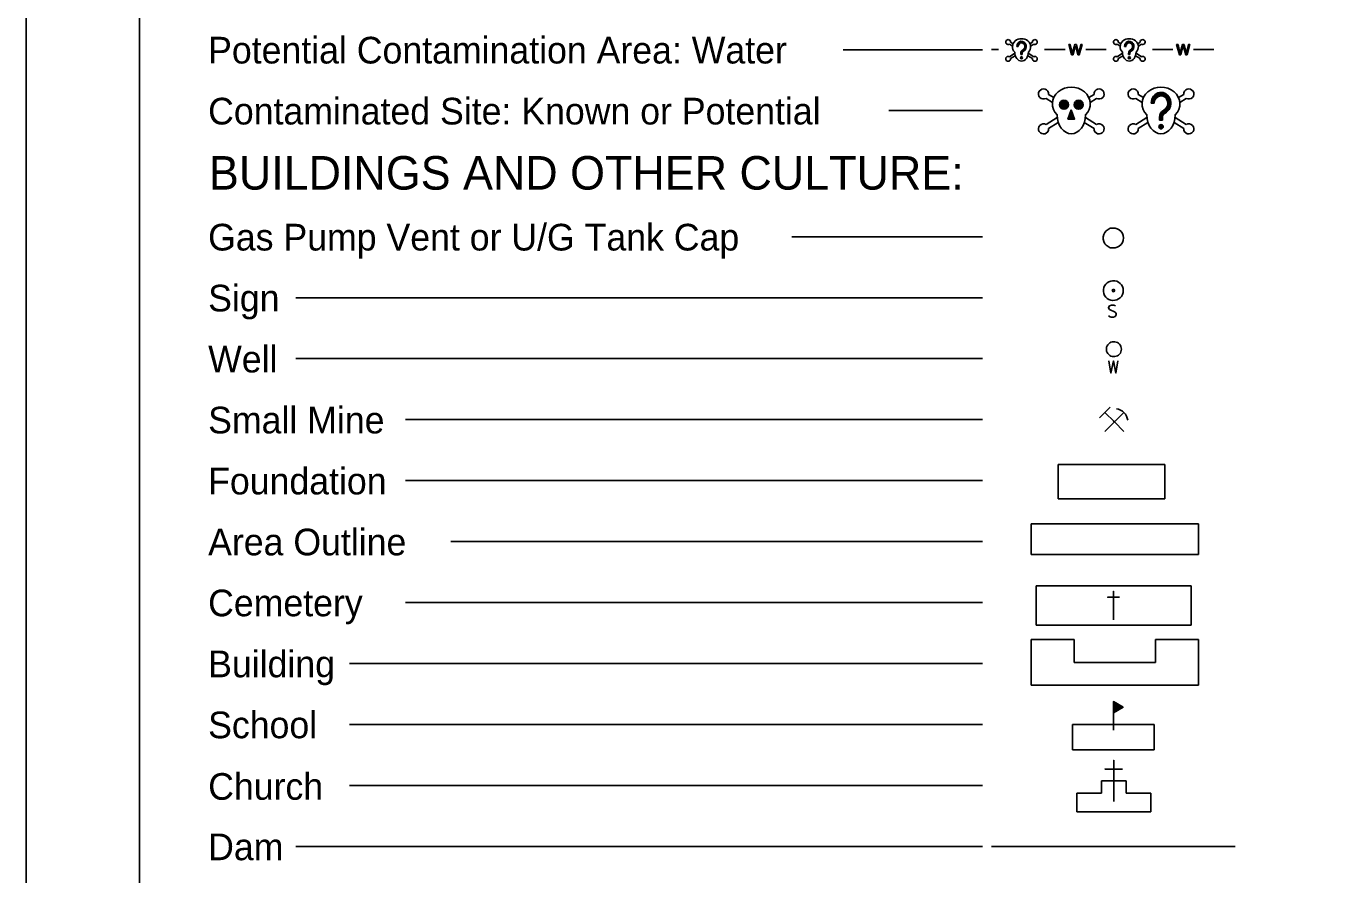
# Model space of a CAD drawing. Extents: x 1855058 to 1858918, y 1540202 to 1542502.
# Drawn here: x 1857118.6 to 1857551.6, y 1541678.1 to 1541959 of the extents above; entities that cross this region are included whole.
import ezdxf

# ---------------------------------------------------------------- set-up
doc = ezdxf.new("R2010")
doc.units = 0
for name, color, linetype in [('Default', 7, 'Continuous'), ('Exist Contamination Potential Cell', 7, 'Continuous'), ('Sheet Data Field CELL', 7, 'Continuous'), ('Sheet Symbology CELL', 7, 'Continuous')]:
    doc.layers.add(name, color=color, linetype=linetype)

msp = doc.modelspace()

# ---------------------------------------------------------------- linework, layer by layer
at = {"layer": 'Default'}
msp.add_lwpolyline([(1857118.6, 1542501.77), (1857118.6, 1541401.77), (1858818.6, 1541401.77), (1858818.6, 1542501.77)], close=True, dxfattribs=at)
at = {"layer": 'Exist Contamination Potential Cell'}
msp.add_line((1857118.6, 1542501.77), (1857118.6, 1541401.77), dxfattribs=at)
at = {"layer": 'Sheet Data Field CELL'}
for p, q in [((1857435.28, 1541951.18), (1857389.09, 1541951.18)), ((1857438.18, 1541951.19), (1857440.51, 1541951.19)), ((1857444.13, 1541953.02), (1857445.15, 1541952.38)), ((1857444.54, 1541953.67), (1857445.36, 1541953.15)), ((1857446.6, 1541952.24), (1857447.08, 1541952.24)), ((1857448.16, 1541951.19), (1857448.16, 1541951.19)), ((1857451.78, 1541953.67), (1857450.95, 1541953.15)), ((1857452.18, 1541953.02), (1857451.16, 1541952.38)), ((1857455.8, 1541951.19), (1857462.59, 1541951.19)), ((1857469.39, 1541951.19), (1857476.18, 1541951.19)), ((1857479.8, 1541953.02), (1857480.82, 1541952.38)), ((1857480.2, 1541953.67), (1857481.03, 1541953.15)), ((1857482.26, 1541952.24), (1857482.75, 1541952.24)), ((1857483.82, 1541951.19), (1857483.82, 1541951.19)), ((1857487.44, 1541953.67), (1857486.62, 1541953.15)), ((1857487.85, 1541953.02), (1857486.83, 1541952.38)), ((1857491.47, 1541951.19), (1857498.26, 1541951.19)), ((1857505.05, 1541951.19), (1857511.85, 1541951.19)), ((1857445.91, 1541949.98), (1857444.13, 1541948.86)), ((1857446.08, 1541949.19), (1857444.54, 1541948.22)), ((1857447.92, 1541949.97), (1857447.92, 1541949.55)), ((1857447.92, 1541949.55), (1857448.4, 1541949.55)), ((1857447.98, 1541949.97), (1857447.98, 1541949.55)), ((1857448.05, 1541949.97), (1857448.05, 1541949.55)), ((1857448.12, 1541949.97), (1857448.12, 1541949.55)), ((1857448.19, 1541949.97), (1857448.19, 1541949.55)), ((1857448.26, 1541949.97), (1857448.26, 1541949.55)), ((1857448.33, 1541949.97), (1857448.33, 1541949.55)), ((1857448.4, 1541949.97), (1857448.4, 1541949.55)), ((1857450.23, 1541949.19), (1857451.78, 1541948.22)), ((1857450.4, 1541949.98), (1857452.18, 1541948.86)), ((1857481.57, 1541949.98), (1857479.8, 1541948.86)), ((1857481.75, 1541949.19), (1857480.2, 1541948.22)), ((1857483.58, 1541949.97), (1857483.58, 1541949.55)), ((1857483.58, 1541949.55), (1857484.06, 1541949.55)), ((1857483.65, 1541949.97), (1857483.65, 1541949.55)), ((1857483.72, 1541949.97), (1857483.72, 1541949.55)), ((1857483.79, 1541949.97), (1857483.79, 1541949.55)), ((1857483.86, 1541949.97), (1857483.86, 1541949.55)), ((1857483.93, 1541949.97), (1857483.93, 1541949.55)), ((1857483.99, 1541949.97), (1857483.99, 1541949.55)), ((1857484.06, 1541949.97), (1857484.06, 1541949.55)), ((1857485.9, 1541949.19), (1857487.44, 1541948.22)), ((1857486.07, 1541949.98), (1857487.85, 1541948.86)), ((1857456.26, 1541935.07), (1857458.37, 1541933.74)), ((1857457.1, 1541936.4), (1857458.81, 1541935.33)), ((1857472.16, 1541936.4), (1857470.44, 1541935.33)), ((1857472.99, 1541935.07), (1857470.88, 1541933.74)), ((1857485.95, 1541935.07), (1857488.07, 1541933.74)), ((1857486.79, 1541936.4), (1857488.5, 1541935.33)), ((1857491.08, 1541933.45), (1857492.08, 1541933.45)), ((1857501.85, 1541936.4), (1857500.13, 1541935.33)), ((1857502.68, 1541935.07), (1857500.57, 1541933.74)), ((1857435.28, 1541931), (1857404.17, 1541931)), ((1857459.95, 1541928.73), (1857456.26, 1541926.41)), ((1857464.63, 1541930.74), (1857464.63, 1541930.74)), ((1857469.3, 1541928.73), (1857472.99, 1541926.41)), ((1857489.64, 1541928.73), (1857485.95, 1541926.41)), ((1857493.82, 1541928.72), (1857493.82, 1541927.84)), ((1857493.96, 1541928.72), (1857493.96, 1541927.84)), ((1857494.1, 1541928.72), (1857494.1, 1541927.84)), ((1857494.25, 1541928.72), (1857494.25, 1541927.84)), ((1857494.32, 1541931.25), (1857494.32, 1541931.25)), ((1857494.39, 1541928.72), (1857494.39, 1541927.84)), ((1857494.53, 1541928.72), (1857494.53, 1541927.84)), ((1857494.68, 1541928.72), (1857494.68, 1541927.84)), ((1857494.82, 1541928.72), (1857494.82, 1541927.84)), ((1857498.99, 1541928.73), (1857502.68, 1541926.41)), ((1857460.31, 1541927.1), (1857457.1, 1541925.08)), ((1857468.94, 1541927.1), (1857472.16, 1541925.08)), ((1857490, 1541927.1), (1857486.79, 1541925.08)), ((1857493.82, 1541927.84), (1857494.82, 1541927.84)), ((1857498.64, 1541927.1), (1857501.85, 1541925.08)), ((1857435.28, 1541889.28), (1857372.14, 1541889.28)), ((1857435.28, 1541869.11), (1857207.84, 1541869.11)), ((1857435.28, 1541848.93), (1857207.84, 1541848.93)), ((1857475.76, 1541831.13), (1857473.93, 1541829.31)), ((1857475.76, 1541824.85), (1857482.04, 1541831.13)), ((1857435.28, 1541828.75), (1857244.16, 1541828.75)), ((1857478.9, 1541827.99), (1857478.54, 1541828.34)), ((1857478.9, 1541827.99), (1857482.04, 1541824.85)), ((1857460.29, 1541813.85), (1857495.6, 1541813.85)), ((1857460.29, 1541802.57), (1857460.29, 1541813.85)), ((1857495.6, 1541813.85), (1857495.6, 1541802.57)), ((1857435.28, 1541808.57), (1857244.16, 1541808.57)), ((1857495.6, 1541802.57), (1857460.29, 1541802.57)), ((1857506.78, 1541794.24), (1857451.29, 1541794.24)), ((1857451.29, 1541794.24), (1857451.29, 1541784.15)), ((1857506.78, 1541784.15), (1857506.78, 1541794.24)), ((1857435.28, 1541788.39), (1857259.25, 1541788.39)), ((1857451.29, 1541784.15), (1857506.78, 1541784.15)), ((1857452.95, 1541773.69), (1857504.27, 1541773.69)), ((1857452.95, 1541760.77), (1857452.95, 1541773.69)), ((1857504.27, 1541773.69), (1857504.27, 1541760.77)), ((1857435.28, 1541768.21), (1857244.16, 1541768.21)), ((1857504.27, 1541760.77), (1857452.95, 1541760.77)), ((1857465.58, 1541755.94), (1857451.29, 1541755.94)), ((1857451.29, 1541755.94), (1857451.29, 1541740.81)), ((1857465.58, 1541748.37), (1857465.58, 1541755.94)), ((1857506.78, 1541755.94), (1857492.49, 1541755.94)), ((1857492.49, 1541755.94), (1857492.49, 1541748.37)), ((1857506.78, 1541740.81), (1857506.78, 1541755.94)), ((1857435.28, 1541748.03), (1857225.71, 1541748.03)), ((1857492.49, 1541748.37), (1857465.58, 1541748.37)), ((1857451.29, 1541740.81), (1857506.78, 1541740.81)), ((1857435.28, 1541727.85), (1857225.71, 1541727.85)), ((1857465.08, 1541727.85), (1857492.05, 1541727.85)), ((1857465.08, 1541719.48), (1857465.08, 1541727.85)), ((1857492.05, 1541727.85), (1857492.05, 1541719.48)), ((1857492.05, 1541719.48), (1857465.08, 1541719.48)), ((1857482.79, 1541709.18), (1857474.62, 1541709.18)), ((1857474.62, 1541709.18), (1857474.62, 1541705.1)), ((1857482.79, 1541705.1), (1857482.79, 1541709.18)), ((1857435.28, 1541707.68), (1857225.71, 1541707.68)), ((1857474.62, 1541705.1), (1857466.45, 1541705.1)), ((1857466.45, 1541705.1), (1857466.45, 1541698.96)), ((1857490.96, 1541705.1), (1857482.79, 1541705.1)), ((1857490.96, 1541698.96), (1857490.96, 1541705.1)), ((1857466.45, 1541698.96), (1857490.96, 1541698.96)), ((1857435.28, 1541687.5), (1857207.84, 1541687.5)), ((1857438.18, 1541687.5), (1857518.9, 1541687.5))]:
    msp.add_line(p, q, dxfattribs=at)
for points in [[(1857465.91, 1541952.08), (1857465.2, 1541949.49), (1857464.74, 1541949.49), (1857463.83, 1541952.89), (1857464.3, 1541952.89), (1857464.81, 1541950.66)], [(1857465.11, 1541950.59), (1857465.76, 1541952.89), (1857466.3, 1541952.89), (1857466.79, 1541951.17)], [(1857467.22, 1541950.71), (1857467.75, 1541952.89), (1857468.2, 1541952.89), (1857467.27, 1541949.49), (1857466.84, 1541949.49), (1857466.13, 1541952.08)], [(1857501.58, 1541952.08), (1857500.86, 1541949.49), (1857500.4, 1541949.49), (1857499.5, 1541952.89), (1857499.96, 1541952.89), (1857500.48, 1541950.66)], [(1857500.78, 1541950.59), (1857501.42, 1541952.89), (1857501.96, 1541952.89), (1857502.45, 1541951.17)], [(1857502.88, 1541950.71), (1857503.42, 1541952.89), (1857503.87, 1541952.89), (1857502.94, 1541949.49), (1857502.5, 1541949.49), (1857501.79, 1541952.08)], [(1857481.93, 1541888.86), (1857481.75, 1541889.66), (1857481.57, 1541890.37), (1857481.12, 1541891), (1857480.49, 1541891.54), (1857479.87, 1541891.9), (1857479.15, 1541892.16), (1857478.35, 1541892.16), (1857477.54, 1541892.07), (1857476.83, 1541891.72), (1857476.2, 1541891.27), (1857475.76, 1541890.73), (1857475.4, 1541890.02), (1857475.22, 1541889.21), (1857475.22, 1541888.5), (1857475.4, 1541887.69), (1857475.76, 1541886.98), (1857476.2, 1541886.44), (1857476.83, 1541886), (1857477.54, 1541885.64), (1857478.35, 1541885.55), (1857479.15, 1541885.55), (1857479.87, 1541885.82), (1857480.49, 1541886.18), (1857481.12, 1541886.71), (1857481.57, 1541887.34), (1857481.75, 1541888.05), (1857481.93, 1541888.86)], [(1857481.83, 1541871.45), (1857481.76, 1541872.1), (1857481.57, 1541872.76), (1857481.24, 1541873.35), (1857480.78, 1541873.81), (1857480.26, 1541874.2), (1857479.67, 1541874.53), (1857479.08, 1541874.66), (1857478.36, 1541874.73), (1857477.7, 1541874.6), (1857477.11, 1541874.4), (1857476.52, 1541874.07), (1857476.06, 1541873.61), (1857475.67, 1541873.02), (1857475.41, 1541872.43), (1857475.28, 1541871.78), (1857475.28, 1541871.12), (1857475.41, 1541870.47), (1857475.67, 1541869.88), (1857476.06, 1541869.29), (1857476.52, 1541868.83), (1857477.11, 1541868.5), (1857477.7, 1541868.3), (1857478.36, 1541868.17), (1857479.08, 1541868.24), (1857479.67, 1541868.37), (1857480.26, 1541868.7), (1857480.78, 1541869.09), (1857481.24, 1541869.55), (1857481.57, 1541870.14), (1857481.76, 1541870.79), (1857481.83, 1541871.45)], [(1857478.69, 1541871.84), (1857478.49, 1541871.84), (1857478.29, 1541871.71), (1857478.16, 1541871.51), (1857478.23, 1541871.32), (1857478.36, 1541871.12), (1857478.55, 1541871.06), (1857478.75, 1541871.12), (1857478.88, 1541871.25), (1857478.95, 1541871.51), (1857478.88, 1541871.71), (1857478.69, 1541871.84)], [(1857479.32, 1541866.4), (1857478.69, 1541866.68), (1857477.96, 1541866.68), (1857477.29, 1541866.4), (1857477, 1541865.89), (1857477, 1541865.7), (1857477.32, 1541865.22), (1857479.16, 1541864.27), (1857479.48, 1541863.82), (1857479.45, 1541863.44), (1857479.16, 1541862.93), (1857478.62, 1541862.65), (1857477.86, 1541862.65), (1857477.51, 1541862.78), (1857477, 1541863.12)], [(1857481.22, 1541852.06), (1857481.15, 1541852.5), (1857481.07, 1541852.94), (1857480.87, 1541853.33), (1857480.59, 1541853.69), (1857480.27, 1541854.01), (1857479.91, 1541854.25), (1857479.48, 1541854.41), (1857479.04, 1541854.53), (1857478.6, 1541854.53), (1857478.17, 1541854.49), (1857477.73, 1541854.33), (1857477.37, 1541854.13), (1857477.02, 1541853.85), (1857476.7, 1541853.53), (1857476.5, 1541853.14), (1857476.34, 1541852.74), (1857476.26, 1541852.3), (1857476.26, 1541851.82), (1857476.34, 1541851.39), (1857476.5, 1541850.99), (1857476.7, 1541850.59), (1857477.02, 1541850.28), (1857477.37, 1541850), (1857477.73, 1541849.8), (1857478.17, 1541849.64), (1857478.6, 1541849.6), (1857479.04, 1541849.6), (1857479.48, 1541849.72), (1857479.91, 1541849.88), (1857480.27, 1541850.12), (1857480.59, 1541850.43), (1857480.87, 1541850.79), (1857481.07, 1541851.19), (1857481.15, 1541851.63), (1857481.22, 1541852.06)], [(1857477.1, 1541848.17), (1857477.74, 1541844.13), (1857478.57, 1541848.17), (1857479.39, 1541844.13), (1857480.09, 1541848.17)], [(1857478.9, 1541827.99), (1857475.76, 1541831.13), (1857477.53, 1541832.9)], [(1857483.3, 1541828.55), (1857483.15, 1541829.26), (1857482.9, 1541829.91), (1857482.54, 1541830.52), (1857482.09, 1541831.03), (1857481.58, 1541831.53), (1857480.97, 1541831.89), (1857480.31, 1541832.19), (1857479.65, 1541832.34)], [(1857478.63, 1541762.51), (1857478.63, 1541771.97), (1857478.63, 1541769.96), (1857476.62, 1541769.96), (1857480.64, 1541769.96)], [(1857478.6, 1541725.98), (1857478.6, 1541735.43), (1857481.77, 1541733.57), (1857478.6, 1541731.71), (1857478.79, 1541732.01), (1857478.79, 1541735.17), (1857481.4, 1541733.53), (1857478.98, 1541732.12), (1857479.01, 1541734.87), (1857481.1, 1541733.53), (1857479.2, 1541732.45), (1857479.2, 1541734.54), (1857480.76, 1541733.53), (1857479.42, 1541732.79), (1857479.42, 1541734.21), (1857480.43, 1541733.57), (1857479.61, 1541733.09), (1857479.61, 1541733.87), (1857480.13, 1541733.57), (1857479.8, 1541733.39), (1857479.76, 1541733.61), (1857479.87, 1541733.57)], [(1857478.7, 1541702.37), (1857478.7, 1541715.99), (1857478.7, 1541713.09), (1857475.81, 1541713.09), (1857481.6, 1541713.09)]]:
    msp.add_lwpolyline(points, dxfattribs=at)
for points in [[(1857464.63, 1541931.25), (1857463.52, 1541928.23), (1857465.73, 1541928.23)], [(1857464.63, 1541930.74), (1857463.77, 1541928.41), (1857465.48, 1541928.41)], [(1857464.63, 1541930.23), (1857464.02, 1541928.59), (1857465.23, 1541928.59)], [(1857464.63, 1541929.71), (1857464.28, 1541928.76), (1857464.97, 1541928.76)], [(1857464.63, 1541929.2), (1857464.53, 1541928.94), (1857464.72, 1541928.94)]]:
    msp.add_lwpolyline(points, close=True, dxfattribs=at)
for centre, radius in [((1857448.17, 1541948.5), 0.344), ((1857448.17, 1541948.5), 0.267), ((1857448.17, 1541948.5), 0.19), ((1857448.17, 1541948.5), 0.113), ((1857448.17, 1541948.5), 0.0367), ((1857483.84, 1541948.5), 0.344), ((1857483.84, 1541948.5), 0.267), ((1857483.84, 1541948.5), 0.19), ((1857483.84, 1541948.5), 0.113), ((1857483.84, 1541948.5), 0.0367), ((1857462.19, 1541932.97), 1.5), ((1857462.19, 1541932.97), 1.32), ((1857462.19, 1541932.97), 1.14), ((1857462.19, 1541932.97), 0.968), ((1857462.19, 1541932.97), 0.791), ((1857462.19, 1541932.97), 0.614), ((1857462.19, 1541932.97), 0.438), ((1857462.19, 1541932.97), 0.261), ((1857462.19, 1541932.97), 0.0847), ((1857467.06, 1541932.97), 1.5), ((1857467.06, 1541932.97), 1.32), ((1857467.06, 1541932.97), 1.14), ((1857467.06, 1541932.97), 0.968), ((1857467.06, 1541932.97), 0.791), ((1857467.06, 1541932.97), 0.614), ((1857467.06, 1541932.97), 0.438), ((1857467.06, 1541932.97), 0.261), ((1857467.06, 1541932.97), 0.0847), ((1857494.35, 1541925.67), 0.715), ((1857494.35, 1541925.67), 0.556), ((1857494.35, 1541925.67), 0.394), ((1857494.35, 1541925.67), 0.235), ((1857494.35, 1541925.67), 0.0762)]:
    msp.add_circle(centre, radius, dxfattribs=at)
for centre, radius, start, end in [((1857443.73, 1541953.72), 0.805, 355.8976, 299.8062), ((1857452.58, 1541953.72), 0.805, 240.1938, 184.1024), ((1857479.4, 1541953.72), 0.805, 355.8976, 299.8062), ((1857488.25, 1541953.72), 0.805, 240.1938, 184.1024), ((1857443.73, 1541948.16), 0.805, 60.1938, 4.1024), ((1857452.58, 1541948.16), 0.805, 175.8976, 119.8062), ((1857479.4, 1541948.16), 0.805, 60.1938, 4.1024), ((1857488.25, 1541948.16), 0.805, 175.8976, 119.8062), ((1857455.43, 1541936.52), 1.67, 355.8976, 299.8062), ((1857473.83, 1541936.52), 1.67, 240.1938, 184.1024), ((1857485.12, 1541936.52), 1.67, 355.8976, 299.8062), ((1857503.52, 1541936.52), 1.67, 240.1938, 184.1024), ((1857455.43, 1541924.96), 1.67, 60.1938, 4.1024), ((1857473.83, 1541924.96), 1.67, 175.8976, 119.8062), ((1857485.12, 1541924.96), 1.67, 60.1938, 4.1024), ((1857503.52, 1541924.96), 1.67, 175.8976, 119.8062)]:
    msp.add_arc(centre, radius, start, end, dxfattribs=at)
for centre, major_axis, ratio, start_param, end_param in [((1857448.16, 1541952.14), (3.02, 0), 0.885014, 5.564242, 10.143721), ((1857483.82, 1541952.14), (3.02, 0), 0.885014, 5.564242, 10.143721), ((1857448.16, 1541950.41), (0, -3.02), 0.752542, 4.722735, 7.843636), ((1857448.16, 1541952.24), (0, 1.73), 0.9, 3.567618, 7.853982), ((1857448.16, 1541952.24), (0, 1.66), 0.9, 3.567618, 7.853982), ((1857448.16, 1541952.24), (0, 1.58), 0.9, 3.567618, 7.853982), ((1857448.16, 1541952.24), (0, 1.5), 0.9, 3.567618, 7.853982), ((1857448.16, 1541952.24), (0, 1.43), 0.9, 3.567618, 7.853982), ((1857448.16, 1541952.24), (0, 1.35), 0.9, 3.567618, 7.853982), ((1857448.16, 1541952.24), (0, 1.27), 0.9, 3.567618, 7.853982), ((1857448.16, 1541952.24), (0, 1.2), 0.9, 3.567618, 7.853982), ((1857449.09, 1541949.97), (0, 1.3), 0.9, 0.426026, 1.570796), ((1857449.09, 1541949.97), (0, 1.22), 0.9, 0.426026, 1.570796), ((1857449.09, 1541949.97), (0, 1.15), 0.9, 0.426026, 1.570796), ((1857449.09, 1541949.97), (0, 1.07), 0.9, 0.426026, 1.570796), ((1857449.09, 1541949.97), (0, 0.994), 0.9, 0.426026, 1.570796), ((1857449.09, 1541949.97), (0, 0.917), 0.9, 0.426026, 1.570796), ((1857449.09, 1541949.97), (0, 0.841), 0.9, 0.426026, 1.570796), ((1857449.09, 1541949.97), (0, 0.764), 0.9, 0.426026, 1.570796), ((1857483.82, 1541950.41), (0, -3.02), 0.752542, 4.722735, 7.843636), ((1857483.82, 1541952.24), (0, 1.73), 0.9, 3.567618, 7.853982), ((1857483.82, 1541952.24), (0, 1.66), 0.9, 3.567618, 7.853982), ((1857483.82, 1541952.24), (0, 1.58), 0.9, 3.567618, 7.853982), ((1857483.82, 1541952.24), (0, 1.5), 0.9, 3.567618, 7.853982), ((1857483.82, 1541952.24), (0, 1.43), 0.9, 3.567618, 7.853982), ((1857483.82, 1541952.24), (0, 1.35), 0.9, 3.567618, 7.853982), ((1857483.82, 1541952.24), (0, 1.27), 0.9, 3.567618, 7.853982), ((1857483.82, 1541952.24), (0, 1.2), 0.9, 3.567618, 7.853982), ((1857484.75, 1541949.97), (0, 1.3), 0.9, 0.426026, 1.570796), ((1857484.75, 1541949.97), (0, 1.22), 0.9, 0.426026, 1.570796), ((1857484.75, 1541949.97), (0, 1.15), 0.9, 0.426026, 1.570796), ((1857484.75, 1541949.97), (0, 1.07), 0.9, 0.426026, 1.570796), ((1857484.75, 1541949.97), (0, 0.994), 0.9, 0.426026, 1.570796), ((1857484.75, 1541949.97), (0, 0.917), 0.9, 0.426026, 1.570796), ((1857484.75, 1541949.97), (0, 0.841), 0.9, 0.426026, 1.570796), ((1857484.75, 1541949.97), (0, 0.764), 0.9, 0.426026, 1.570796), ((1857464.63, 1541933.24), (6.28, 0), 0.885014, 5.564242, 10.143721), ((1857494.32, 1541933.24), (6.28, 0), 0.885014, 5.564242, 10.143721), ((1857494.32, 1541933.45), (0, 3.6), 0.9, 3.567618, 7.853982), ((1857494.32, 1541933.45), (0, 3.44), 0.9, 3.567618, 7.853982), ((1857494.32, 1541933.45), (0, 3.28), 0.9, 3.567618, 7.853982), ((1857494.32, 1541933.45), (0, 3.13), 0.9, 3.567618, 7.853982), ((1857494.32, 1541933.45), (0, 2.97), 0.9, 3.567618, 7.853982), ((1857494.32, 1541933.45), (0, 2.81), 0.9, 3.567618, 7.853982), ((1857494.32, 1541933.45), (0, 2.65), 0.9, 3.567618, 7.853982), ((1857494.32, 1541933.45), (0, 2.49), 0.9, 3.567618, 7.853982), ((1857464.63, 1541929.64), (0, -6.28), 0.752542, 4.722735, 7.843636), ((1857494.32, 1541929.64), (0, -6.28), 0.752542, 4.722735, 7.843636), ((1857496.25, 1541928.72), (0, 2.7), 0.9, 0.426026, 1.570796), ((1857496.25, 1541928.72), (0, 2.54), 0.9, 0.426026, 1.570796), ((1857496.25, 1541928.72), (0, 2.38), 0.9, 0.426026, 1.570796), ((1857496.25, 1541928.72), (0, 2.22), 0.9, 0.426026, 1.570796), ((1857496.25, 1541928.72), (0, 2.07), 0.9, 0.426026, 1.570796), ((1857496.25, 1541928.72), (0, 1.91), 0.9, 0.426026, 1.570796), ((1857496.25, 1541928.72), (0, 1.75), 0.9, 0.426026, 1.570796), ((1857496.25, 1541928.72), (0, 1.59), 0.9, 0.426026, 1.570796)]:
    msp.add_ellipse(centre, major_axis=major_axis, ratio=ratio, start_param=start_param, end_param=end_param, dxfattribs=at)
for points in [[(1857464.81, 1541950.66), (1857464.9, 1541950.31), (1857464.96, 1541949.97)], [(1857464.96, 1541949.97), (1857465.09, 1541950.51), (1857465.11, 1541950.59)], [(1857466.02, 1541952.48), (1857465.96, 1541952.24), (1857465.91, 1541952.08)], [(1857466.13, 1541952.08), (1857466.03, 1541952.4), (1857466.02, 1541952.48)], [(1857466.79, 1541951.17), (1857466.97, 1541950.53), (1857467.05, 1541949.97)], [(1857467.05, 1541949.97), (1857467.12, 1541950.29), (1857467.22, 1541950.71)], [(1857500.48, 1541950.66), (1857500.56, 1541950.31), (1857500.62, 1541949.97)], [(1857500.62, 1541949.97), (1857500.75, 1541950.51), (1857500.78, 1541950.59)], [(1857501.68, 1541952.48), (1857501.63, 1541952.24), (1857501.58, 1541952.08)], [(1857501.79, 1541952.08), (1857501.7, 1541952.4), (1857501.68, 1541952.48)], [(1857502.45, 1541951.17), (1857502.63, 1541950.53), (1857502.71, 1541949.97)], [(1857502.71, 1541949.97), (1857502.78, 1541950.29), (1857502.88, 1541950.71)]]:
    msp.add_open_spline(points, degree=2, dxfattribs=at)
at = {"layer": 'Sheet Symbology CELL'}
msp.add_line((1857156.1, 1541439.27), (1857156.1, 1542464.27), dxfattribs=at)

# ---------------------------------------------------------------- texts
at = {"layer": 'Sheet Data Field CELL'}
for s, height, p in [('Potential Contamination Area: Water', 8.8282, (1857178.85, 1541946.61)), ('Contaminated Site: Known or Potential', 8.8282, (1857178.85, 1541926.43)), ('BUILDINGS AND OTHER CULTURE:', 11.0983, (1857179.13, 1541904.87)), ('Gas Pump Vent or U/G Tank Cap', 8.8282, (1857178.85, 1541884.72)), ('Sign', 8.828, (1857178.86, 1541864.55)), ('Well', 8.828, (1857178.86, 1541844.37)), ('Small Mine', 8.828, (1857178.86, 1541824.18)), ('Foundation', 8.828, (1857178.86, 1541804)), ('Area Outline', 8.8282, (1857178.86, 1541783.83)), ('Cemetery', 8.828, (1857178.85, 1541763.66)), ('Building', 8.828, (1857178.86, 1541743.48)), ('School', 8.828, (1857178.85, 1541723.3)), ('Church', 8.828, (1857178.87, 1541702.93)), ('Dam', 8.828, (1857178.86, 1541682.94))]:
    msp.add_text(s, height=height, dxfattribs=at).set_placement(p)

doc.saveas('drawing.dxf')
